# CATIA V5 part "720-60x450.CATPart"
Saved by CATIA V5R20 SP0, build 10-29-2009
Part number: 720-60x450
Definition: NONE
Nomenclature: 720-60x450
Source: Unknown
Description: 720-60x450
Bounding box of the stored display mesh (mm): x 0 to 450, y -30 to 30, z -30 to 30
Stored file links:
  C:\Users\Utente\Desktop\IO LAVORO\3D X SITO CF\X SITO\720\720-60x450.CATPart
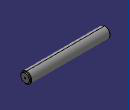
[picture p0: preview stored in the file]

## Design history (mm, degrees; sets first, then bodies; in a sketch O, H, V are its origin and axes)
Body1 "720-60x450" (main body)
  Solid1: solid without history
